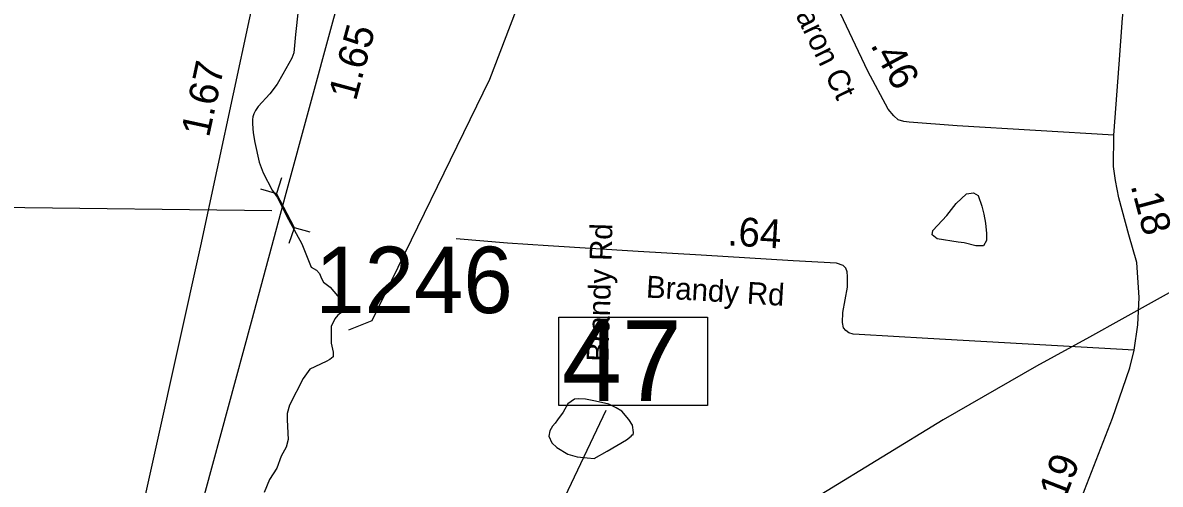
# Model space of a CAD drawing. Extents: x 1662474 to 1856135, y 779280 to 917889.
# Drawn here: x 1735344 to 1740276, y 808812 to 810813 of the extents above; entities that cross this region are included whole.
import ezdxf

# ---------------------------------------------------------------- set-up
doc = ezdxf.new("R2010")
doc.units = 0
for name, color, linetype in [('Cogo Default Point CELL', 7, 'Continuous'), ('Exist Hydrographic Creek Single Shore', 7, 'Continuous'), ('Exist Hydrographic Misc Water Feature', 7, 'Continuous'), ('Exist Hydrographic Pond Under 1500 Sq Ft', 7, 'Continuous'), ('Exist Road Non-System Type 51 Label', 7, 'Continuous'), ('Exist Road Primary Interstate Divided Center Attributed', 7, 'Continuous'), ('Exist Road Primary Interstate Mileage Hundredths English Label', 7, 'Continuous'), ('Exist Road Primary Interstate Structure Culvert CELL', 7, 'Continuous'), ('Exist Road Primary Interstate Structure Culvert Number Label', 7, 'Continuous'), ('Exist Road Secondary Mileage Tenths English Label', 7, 'Continuous'), ('Exist Road Secondary Structure Standard Bridge Number Label', 7, 'Continuous'), ('Exist Road Secondary Type 51 Attributed', 7, 'Continuous'), ('Exist Road Secondary Type 51 Label', 7, 'Continuous'), ('Exist Utilities Electrical Transmission Line', 7, 'Continuous'), ('Prop DGN Element Guardrail', 7, 'Continuous')]:
    doc.layers.add(name, color=color, linetype=linetype)

msp = doc.modelspace()

# ---------------------------------------------------------------- linework, layer by layer
at = {"layer": 'Exist Hydrographic Creek Single Shore'}
for points in [[(1736538.6, 810868.2), (1736527.1, 810762.2), (1736518.5, 810683.2), (1736509.8, 810659.6), (1736472.2, 810590.1), (1736446.8, 810547.2), (1736414.8, 810505.6), (1736365.1, 810450.2), (1736352.9, 810432.1), (1736346, 810417.9), (1736341.2, 810404.5), (1736339.8, 810393.8)], [(1736339.8, 810393.8), (1736339.5, 810374.3), (1736342.4, 810336), (1736350.2, 810294.5), (1736368.4, 810209.2), (1736386.8, 810162.8), (1736425.8, 810087.7), (1736447.4, 810056.8), (1736496.6, 809960.4), (1736553.6, 809854.4), (1736594.5, 809752.8), (1736616.9, 809739.9), (1736631.2, 809725.2), (1736639.8, 809704.2), (1736648.4, 809688), (1736676.8, 809665.9), (1736708.8, 809629.4), (1736729.8, 809601.4), (1736732.6, 809584.8), (1736731.6, 809560.4), (1736710.6, 809545.4), (1736696.4, 809528.7), (1736681.1, 809496.4), (1736681.4, 809423.4), (1736690.4, 809384.6), (1736690.1, 809364.9), (1736674.9, 809353.1), (1736660.1, 809344.4), (1736588.5, 809310.3), (1736559.9, 809270.9), (1736499.8, 809155.2), (1736490.6, 809118.9), (1736490.6, 809091.1), (1736494.2, 809006.1), (1736486.6, 808973), (1736463.9, 808933.1), (1736445.5, 808881.7), (1736413.8, 808832.6), (1736390.6, 808775.6)]]:
    msp.add_lwpolyline(points, dxfattribs=at)
at = {"layer": 'Exist Hydrographic Misc Water Feature'}
msp.add_lwpolyline([(1736757.7, 809481.8), (1736858.6, 809522.4), (1737368.6, 810568.9), (1737573.6, 811106.4), (1737843.7, 812279.2), (1737911.8, 812445.2), (1738129.7, 812545.8), (1738221.6, 812668.7), (1738326.8, 813152.3), (1738534.8, 813446.8), (1738551.8, 813486.4), (1738563.1, 813539.2), (1738582.9, 813606.1), (1738657.7, 813749.6), (1739010.6, 814087), (1739087.7, 814252.8), (1739116.6, 814659.3), (1739184.7, 814808.9), (1739310.6, 814924.4), (1739628.7, 815105), (1740172.7, 815274.5), (1740314.8, 815399.7)], dxfattribs=at)
at = {"layer": 'Exist Hydrographic Pond Under 1500 Sq Ft'}
for points in [[(1739399.5, 809861.8), (1739309.2, 809875.9), (1739287.3, 809892.7), (1739289.9, 809912), (1739350.5, 809976.5), (1739390.5, 810029.3), (1739435.6, 810070.6), (1739466.6, 810075.7), (1739487.2, 810064.1), (1739502.7, 810017.7), (1739511.7, 809982.9), (1739518.1, 809944.3), (1739523.3, 809899.1), (1739523.3, 809868.2), (1739510.4, 809845), (1739476.9, 809845), (1739425.3, 809859.2), (1739399.5, 809861.8)], [(1737986.6, 809025.9), (1737990.3, 809025.7), (1737992.5, 809035.9), (1737987, 809068), (1737971.2, 809092.1), (1737941.5, 809128.4), (1737917.5, 809142.7), (1737885.7, 809158.9), (1737827.9, 809171.5), (1737784, 809179.9), (1737753.9, 809182.2), (1737735.8, 809180.4), (1737707.7, 809160.6), (1737687.2, 809124.8), (1737663, 809091.1), (1737653, 809077.1)], [(1737653, 809077.1), (1737640.9, 809063.2), (1737628.6, 809043.3), (1737624.3, 809019.5), (1737638, 808991.3), (1737660, 808971.1), (1737707.7, 808942.6), (1737747.5, 808930.2), (1737791.6, 808925.8), (1737821.5, 808923.5), (1737877.7, 808955), (1737962.2, 809004.2), (1737982.5, 809020), (1737986.6, 809025.9)]]:
    msp.add_lwpolyline(points, dxfattribs=at)
at = {"layer": 'Exist Road Primary Interstate Divided Center Attributed'}
for points in [[(1735507.6, 806511.1), (1735560.9, 806651), (1735688.4, 807114), (1735922.1, 807963.5), (1736136.8, 808780.9), (1736335.3, 809516.4), (1736486.5, 810074.7), (1736688, 810817), (1736962.5, 811815.2), (1737084.6, 812265.7), (1737151.1, 812468.3), (1737242.3, 812702.5), (1737417.3, 813106.2), (1737544.3, 813346), (1737717.7, 813632.3), (1737913.6, 813922.3), (1738197.2, 814284.7), (1738387.5, 814514.3), (1738424.7, 814555.1), (1738463.3, 814598)], [(1737222.5, 813372.5), (1737166.6, 813288.8), (1736982, 812961), (1736848.6, 812673.5), (1736720.6, 812376.6), (1736531.7, 811777.6), (1736437.5, 811342.4), (1736327.5, 810834.4), (1736114.4, 809845.7), (1735826.6, 808548.5), (1735551.4, 807268.4), (1735389.7, 806623.9), (1735348.6, 806481.6)]]:
    msp.add_lwpolyline(points, dxfattribs=at)
at = {"layer": 'Exist Road Primary Interstate Structure Culvert CELL'}
for p, q in [((1736466.3, 810140.3), (1736443.4, 810073.3)), ((1736375.3, 810092.6), (1736443.4, 810073.3)), ((1736521.6, 809923.9), (1736443.4, 810073.3)), ((1736498.7, 809857), (1736521.6, 809923.9)), ((1736589.7, 809904.7), (1736521.6, 809923.9))]:
    msp.add_line(p, q, dxfattribs=at)
at = {"layer": 'Exist Road Primary Interstate Structure Culvert Number Label'}
msp.add_line((1736423.7, 809997.8), (1733262.2, 810036.4), dxfattribs=at)
at = {"layer": 'Exist Road Secondary Structure Standard Bridge Number Label'}
msp.add_line((1736790.5, 806854.3), (1737873.7, 809133.6), dxfattribs=at)
msp.add_lwpolyline([(1737668.8, 809535.7), (1738312.9, 809535.7), (1738312.9, 809153.4), (1737668.8, 809153.4)], close=True, dxfattribs=at)
at = {"layer": 'Exist Road Secondary Type 51 Attributed'}
for points in [[(1740074.2, 810325.9), (1740097.3, 810633.8), (1740112.7, 810832.4), (1740126.5, 810977.1), (1740146.5, 811094.2), (1740160.4, 811174.2), (1740188.1, 811265.1), (1740214.3, 811352.8), (1740248.2, 811439), (1740289.7, 811519.1), (1740352.9, 811640.7), (1740543.7, 812007.3), (1740747.6, 812408.1), (1740874, 812657.2), (1740973.4, 812848.9), (1741087.2, 813045.3), (1741167.9, 813157), (1741248.6, 813250.1), (1741314.7, 813339.8)], [(1740074.2, 810325.9), (1739395.7, 810365.9), (1739187.6, 810382.4), (1739164.9, 810384.3), (1739140.2, 810392.5), (1739121.6, 810409), (1739096.9, 810437.9), (1739008.2, 810602.8), (1738861.7, 810912), (1738729.7, 811171.7), (1738629.9, 811362.5), (1738605.1, 811397.6), (1738578.3, 811430.5), (1738551.5, 811451.2), (1738476.4, 811482.1), (1738387.7, 811488.3), (1738299, 811492.4)], [(1740163.5, 809392.8), (1740178.9, 809503.7), (1740184.3, 809622.2), (1740174, 809772.7), (1740139.3, 809892.9), (1740096.5, 810053.8), (1740082.3, 810129.2), (1740074.1, 810190.3), (1740074.2, 810325.9)], [(1740163.5, 809392.8), (1739268.1, 809444.4), (1738971, 809460.5), (1738944.8, 809462.1), (1738926.3, 809469), (1738913.2, 809479), (1738902.5, 809489.8), (1738897.9, 809512.9), (1738900.2, 809556), (1738919.4, 809666.9), (1738919.4, 809713.1), (1738918.6, 809732.3), (1738912.5, 809749.2), (1738901.7, 809760), (1738872.4, 809770), (1738684.6, 809780.8), (1738285.8, 809804.7), (1738012.5, 809821.6), (1737622.2, 809845.5), (1737445.2, 809857.8), (1737223.4, 809876.3)], [(1739812.1, 808426.8), (1739880.2, 808601.4), (1739947.9, 808786.2), (1740069.6, 809098.7), (1740144.2, 809316.6), (1740163.5, 809392.8)]]:
    msp.add_lwpolyline(points, dxfattribs=at)
at = {"layer": 'Exist Utilities Electrical Transmission Line'}
msp.add_lwpolyline([(1740390.3, 809683.9), (1739969, 809449.9), (1739739.3, 809323.3), (1739334.1, 809091.3), (1738805.6, 808766.9)], dxfattribs=at)

# ---------------------------------------------------------------- texts
at = {"layer": 'Cogo Default Point CELL'}
msp.add_text('1246', height=288, dxfattribs=at).set_placement((1736611.8, 809554))
at = {"layer": 'Exist Road Non-System Type 51 Label'}
msp.add_text('Brandy Rd', height=95, rotation=88.3299, dxfattribs=at).set_placement((1737883.5, 809341.6))
at = {"layer": 'Exist Road Primary Interstate Mileage Hundredths English Label'}
for s, rotation, p in [('1.65', 74.8188, (1736788.2, 810470.3)), ('1.67', 77.8383, (1736151, 810312.4))]:
    msp.add_text(s, height=125, rotation=rotation, dxfattribs=at).set_placement(p)
at = {"layer": 'Exist Road Secondary Mileage Tenths English Label'}
msp.add_text('.64', height=125, rotation=356.5245, dxfattribs=at).set_placement((1738397.7, 809848.1))
at = {"layer": 'Exist Road Secondary Structure Standard Bridge Number Label'}
msp.add_text('47', height=350, dxfattribs=at).set_placement((1737681.3, 809173.2))
at = {"layer": 'Exist Road Secondary Type 51 Label'}
for s, rotation, p in [('Cimmaron Ct', 295.9739, (1738548.3, 811144.2)), ('Brandy Rd', 356.5014, (1738044.7, 809621.8))]:
    msp.add_text(s, height=95, rotation=rotation, dxfattribs=at).set_placement(p)
at = {"layer": 'Prop DGN Element Guardrail'}
for s, rotation, p in [('.46', 298.2747, (1739017.5, 810717.3)), ('.18', 284.896, (1740147, 810107.2)), ('.19', 68.7359, (1739845.5, 808695.3))]:
    msp.add_text(s, height=125, rotation=rotation, dxfattribs=at).set_placement(p)

doc.saveas('drawing.dxf')
